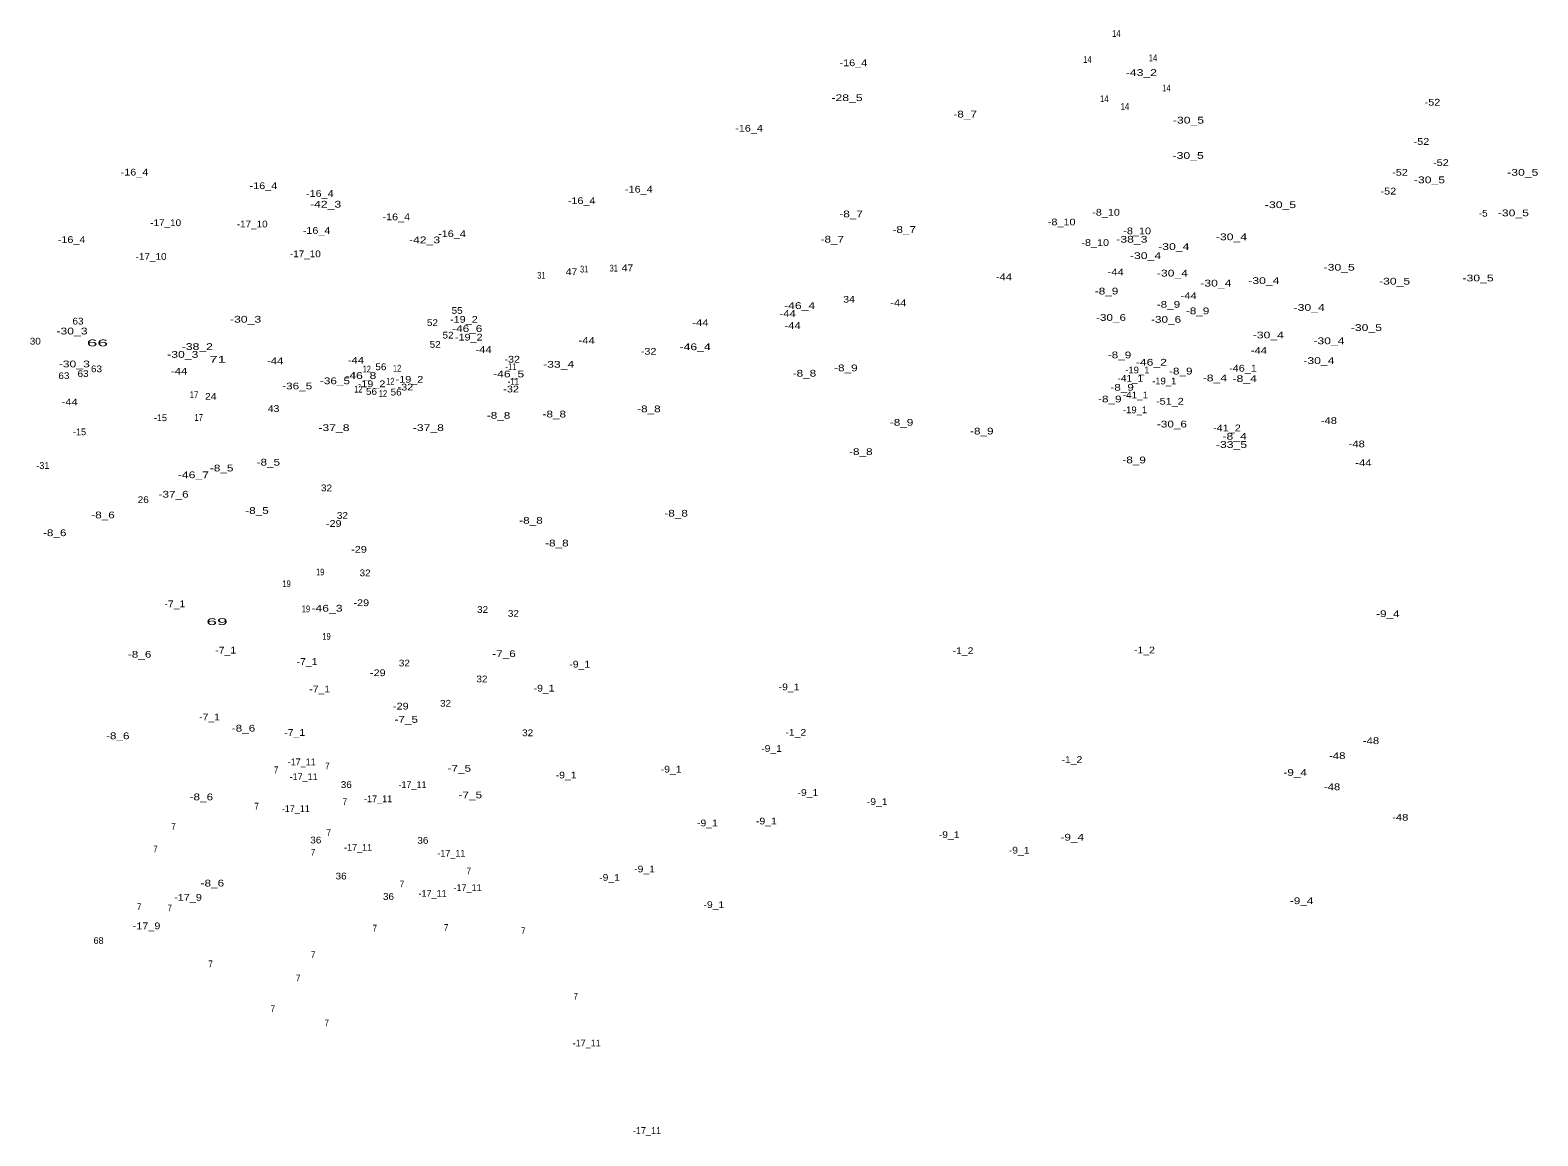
# Model space of a CAD drawing. Extents: x -663241 to -661169, y -1003538 to -1000899.
# Drawn here: x -662062 to -661169, y -1002212 to -1001556 of the extents above; entities that cross this region are included whole.
import ezdxf
from ezdxf.enums import TextEntityAlignment as Align

# ---------------------------------------------------------------- set-up
doc = ezdxf.new("R2010")
doc.units = 0
doc.header["$LTSCALE"] = 1.6
doc.layers.add('24', color=7, linetype='Continuous')

msp = doc.modelspace()

# ---------------------------------------------------------------- texts
at = {"layer": '24'}
for s, width, p in [('14', 0.85, (-661418.459, -1001560.33)), ('-16_4', 1.2, (-661574.25, -1001577.69)), ('14', 0.85, (-661435.569, -1001575.72)), ('14', 0.85, (-661396.74, -1001574.76)), ('-43_2', 1.35, (-661403.58, -1001583.46)), ('14', 0.85, (-661388.76, -1001592.64)), ('-28_5', 1.35, (-661578, -1001598.37)), ('14', 0.85, (-661425.569, -1001598.99)), ('14', 0.85, (-661413.37, -1001603.6)), ('-52', 1.2, (-661231.11, -1001601.06)), ('-8_7', 1.3, (-661508.01, -1001608.11)), ('-30_5', 1.35, (-661375.679, -1001611.68)), ('-16_4', 1.2, (-661636.07, -1001616.49)), ('-52', 1.2, (-661237.65, -1001624.33)), ('-30_5', 1.35, (-661375.87, -1001632.62)), ('-52', 1.2, (-661226.11, -1001636.83)), ('-16_4', 1.2, (-662000.23, -1001642.49)), ('-52', 1.2, (-661250.33, -1001642.6)), ('-30_5', 1.35, (-661232.9, -1001647.05)), ('-30_5', 1.35, (-661177.6, -1001642.63)), ('-16_4', 1.2, (-661923.81, -1001650.55)), ('-16_4', 1.2, (-661890.4, -1001655.16)), ('-16_4', 1.2, (-661701.36, -1001652.6)), ('-52', 1.2, (-661257.25, -1001653.75)), ('-42_3', 1.35, (-661886.98, -1001661.5)), ('-16_4', 1.2, (-661735.26, -1001659.39)), ('-8_7', 1.3, (-661575.59, -1001667.27)), ('-8_10', 1.2, (-661424.52, -1001666.27)), ('-30_5', 1.35, (-661321.15, -1001661.81)), ('-5', 1.1, (-661201.04, -1001666.84)), ('-30_5', 1.35, (-661183.169, -1001666.64)), ('-17_10', 1.1, (-661981.74, -1001672.48)), ('-17_10', 1.1, (-661930.471, -1001673.25)), ('-16_4', 1.2, (-661845.09, -1001668.99)), ('-8_7', 1.3, (-661544.11, -1001676.49)), ('-8_10', 1.2, (-661450.819, -1001672.03)), ('-16_4', 1.2, (-662037.48, -1001682.44)), ('-16_4', 1.2, (-661892.33, -1001677.06)), ('-42_3', 1.35, (-661828.34, -1001682.65)), ('-16_4', 1.2, (-661812.07, -1001678.98)), ('-8_7', 1.3, (-661586.73, -1001682.25)), ('-8_10', 1.2, (-661430.949, -1001684.23)), ('-38_3', 1.35, (-661409.24, -1001682.27)), ('-8_10', 1.2, (-661406.079, -1001677.32)), ('-30_4', 1.35, (-661350.22, -1001680.84)), ('-17_10', 1.1, (-661990.38, -1001692.46)), ('-17_10', 1.1, (-661898.981, -1001690.92)), ('-30_4', 1.35, (-661401.14, -1001691.98)), ('-30_4', 1.35, (-661384.39, -1001686.6)), ('47', 1.15, (-661741.26, -1001701.51)), ('31', 0.8, (-661733.76, -1001699.96)), ('31', 0.8, (-661716.26, -1001699.38)), ('47', 1.15, (-661708.1, -1001699.2)), ('-44', 1.25, (-661418.829, -1001701.66)), ('-30_4', 1.35, (-661385.2, -1001702.35)), ('-30_5', 1.35, (-661286.39, -1001698.88)), ('31', 0.8, (-661759.14, -1001703.62)), ('-44', 1.25, (-661485.059, -1001704.53)), ('-30_4', 1.35, (-661359.47, -1001708.28)), ('-30_4', 1.35, (-661331.02, -1001706.77)), ('-30_5', 1.35, (-661253.559, -1001707.14)), ('-30_5', 1.35, (-661204.1, -1001705.25)), ('34', 1.15, (-661576.809, -1001717.85)), ('-44', 1.25, (-661547.61, -1001719.93)), ('-8_9', 1.3, (-661424.22, -1001712.99)), ('-8_9', 1.3, (-661387.55, -1001720.87)), ('-44', 1.25, (-661375.579, -1001715.69)), ('-30_3', 1.35, (-661934.4, -1001729.67)), ('-19_2', 1.2, (-661805.03, -1001729.74)), ('55', 1.1, (-661809.059, -1001724.48)), ('-44', 1.25, (-661613.169, -1001726.27)), ('-46_4', 1.35, (-661606.12, -1001721.58)), ('-30_6', 1.3, (-661421.59, -1001728.63)), ('-30_6', 1.3, (-661388.95, -1001729.78)), ('-8_9', 1.3, (-661370.27, -1001724.71)), ('-30_4', 1.35, (-661304.17, -1001722.71)), ('-30_3', 1.35, (-662037.26, -1001736.69)), ('63', 1.1, (-662033.68, -1001730.81)), ('52', 1.1, (-661823.669, -1001731.69)), ('-46_6', 1.3, (-661803.041, -1001735.23)), ('-44', 1.25, (-661664.88, -1001731.66)), ('-44', 1.25, (-661610.28, -1001733.39)), ('-30_4', 1.35, (-661328.37, -1001739.02)), ('-30_5', 1.35, (-661270.27, -1001734.61)), ('30', 1.1, (-662058.99, -1001742.67)), ('66', 2.1, (-662022.171, -1001743.69)), ('-38_2', 1.35, (-661962.98, -1001745.87)), ('52', 1.1, (-661822.04, -1001744.58)), ('52', 1.1, (-661814.439, -1001739.1)), ('-19_2', 1.2, (-661802.15, -1001740.31)), ('-44', 1.25, (-661793.39, -1001747.62)), ('-44', 1.25, (-661732.26, -1001742.23)), ('-46_4', 1.35, (-661668.02, -1001746)), ('-30_4', 1.35, (-661292.46, -1001742.47)), ('-30_3', 1.35, (-662035.91, -1001756.18)), ('-30_3', 1.35, (-661971.62, -1001750.52)), ('71', 1.65, (-661950.903, -1001753.43)), ('-44', 1.25, (-661916.86, -1001754.35)), ('-44', 1.25, (-661869, -1001753.96)), ('-32', 1.2, (-661776.4, -1001753.37)), ('-33_4', 1.35, (-661748.87, -1001756.38)), ('-32', 1.2, (-661695.6, -1001748.67)), ('-8_9', 1.3, (-661416.54, -1001750.83)), ('-46_2', 1.35, (-661397.67, -1001755.17)), ('-44', 1.25, (-661333.939, -1001748.16)), ('-30_4', 1.35, (-661298.41, -1001754.19)), ('63', 1.1, (-662042.04, -1001763.12)), ('63', 1.1, (-662030.7, -1001761.87)), ('63', 1.1, (-662022.72, -1001759.08)), ('-44', 1.25, (-661973.76, -1001760.5)), ('-46_8', 1.35, (-661866.12, -1001763.02)), ('12', 0.8, (-661862.569, -1001759.2)), ('56', 1.1, (-661854.21, -1001757.86)), ('12', 0.8, (-661844.6, -1001758.72)), ('-19_2', 1.2, (-661837.291, -1001765.28)), ('-46_5', 1.35, (-661778.54, -1001762.12)), ('-11', 0.85, (-661777.171, -1001757.79)), ('-8_8', 1.3, (-661603.24, -1001761.69)), ('-8_9', 1.3, (-661578.69, -1001758.51)), ('-41_1', 1.1, (-661410.14, -1001764.66)), ('-19_1', 1.05, (-661405.99, -1001759.76)), ('-8_9', 1.3, (-661380.25, -1001760.43)), ('-8_4', 1.35, (-661360.03, -1001764.48)), ('-46_1', 1.2, (-661343.39, -1001758.69)), ('-8_4', 1.35, (-661342.37, -1001764.86)), ('17', 0.85, (-661964.91, -1001774.35)), ('-36_5', 1.3, (-661903.81, -1001769.25)), ('-36_5', 1.3, (-661881.42, -1001766.17)), ('12', 0.8, (-661867.569, -1001771.12)), ('-19_2', 1.2, (-661859.75, -1001767.96)), ('56', 1.1, (-661859.79, -1001772.47)), ('12', 0.8, (-661852.959, -1001773.71)), ('12', 0.8, (-661848.64, -1001766.41)), ('56', 1.1, (-661845.18, -1001772.86)), ('-32', 1.2, (-661839.71, -1001769.89)), ('-32', 1.2, (-661777.07, -1001771.05)), ('-11', 0.85, (-661775.731, -1001766.54)), ('-8_9', 1.3, (-661415, -1001770.04)), ('-41_1', 1.1, (-661407.069, -1001774.57)), ('-19_1', 1.05, (-661390.051, -1001766.29)), ('-44', 1.25, (-662038.61, -1001778.69)), ('24', 1.15, (-661955, -1001775.38)), ('43', 1.15, (-661917.78, -1001782.61)), ('-8_8', 1.3, (-661695.4, -1001782.81)), ('-8_9', 1.3, (-661422.3, -1001776.95)), ('-19_1', 1.05, (-661407.331, -1001783.38)), ('-51_2', 1.2, (-661386.689, -1001778.28)), ('17', 0.85, (-661962.12, -1001787.9)), ('-8_8', 1.3, (-661784.49, -1001786.66)), ('-8_8', 1.3, (-661751.47, -1001785.89)), ('-8_9', 1.3, (-661545.67, -1001790.78)), ('-30_6', 1.3, (-661385.5, -1001791.82)), ('-48', 1.25, (-661292.52, -1001789.74)), ('-37_8', 1.35, (-661882.03, -1001793.96)), ('-37_8', 1.35, (-661826.09, -1001793.96)), ('-8_9', 1.3, (-661498.14, -1001795.97)), ('-41_2', 1.2, (-661352.88, -1001794.08)), ('-8_4', 1.35, (-661348.33, -1001799.06)), ('-8_8', 1.3, (-661569.829, -1001808.17)), ('-33_5', 1.35, (-661350.189, -1001803.93)), ('-48', 1.25, (-661275.99, -1001803.58)), ('-8_5', 1.3, (-661948.549, -1001817.88)), ('-8_5', 1.3, (-661920.9, -1001814.42)), ('-8_9', 1.3, (-661407.9, -1001813.06)), ('-44', 1.25, (-661272.04, -1001814.7)), ('-46_7', 1.35, (-661965.311, -1001821.88)), ('26', 1.1, (-661995.01, -1001836.6)), ('-37_6', 1.3, (-661977.03, -1001833.39)), ('32', 1.1, (-661886.429, -1001829.63)), ('-8_6', 1.3, (-662018.87, -1001845.67)), ('-8_5', 1.3, (-661927.62, -1001843.04)), ('32', 1.1, (-661877.01, -1001845.97)), ('-8_8', 1.3, (-661679.28, -1001844.66)), ('-29', 1.2, (-661882.15, -1001850.75)), ('-8_8', 1.3, (-661765.29, -1001848.89)), ('-8_6', 1.3, (-662047.48, -1001856.23)), ('-8_8', 1.3, (-661749.929, -1001862.33)), ('-29', 1.2, (-661867.17, -1001866.06)), ('19', 0.8, (-661890.191, -1001879.5)), ('32', 1.1, (-661863.559, -1001880.01)), ('19', 0.8, (-661910.091, -1001886.42)), ('-7_1', 1.15, (-661976.31, -1001898.36)), ('-29', 1.2, (-661865.83, -1001897.72)), ('19', 0.8, (-661898.65, -1001901.33)), ('-46_3', 1.35, (-661886.15, -1001900.96)), ('32', 1.1, (-661793.97, -1001901.72)), ('32', 1.1, (-661775.699, -1001904.02)), ('-9_4', 1.3, (-661257.54, -1001904.2)), ('69', 2.1, (-661951.301, -1001908.9)), ('19', 0.8, (-661886.441, -1001917.67)), ('-7_1', 1.15, (-661946.16, -1001925.82)), ('-1_2', 1.15, (-661509.27, -1001926.11)), ('-1_2', 1.15, (-661401.75, -1001925.72)), ('-8_6', 1.3, (-661997.17, -1001928.26)), ('-7_1', 1.15, (-661897.97, -1001932.55)), ('32', 1.1, (-661840.299, -1001933.45)), ('-7_6', 1.3, (-661781.26, -1001927.92)), ('-9_1', 1.15, (-661736.39, -1001934.13)), ('-29', 1.2, (-661856.04, -1001939.21)), ('32', 1.1, (-661794.35, -1001942.87)), ('-7_1', 1.15, (-661890.48, -1001948.87)), ('-9_1', 1.15, (-661757.51, -1001948.34)), ('-9_1', 1.15, (-661612.351, -1001947.58)), ('-29', 1.2, (-661842.4, -1001959)), ('32', 1.1, (-661815.88, -1001957.29)), ('-7_1', 1.15, (-661955.76, -1001965.39)), ('-7_5', 1.3, (-661839.21, -1001966.85)), ('-8_6', 1.3, (-662010.13, -1001976.59)), ('-8_6', 1.3, (-661935.63, -1001972.06)), ('-7_1', 1.15, (-661905.27, -1001974.61)), ('32', 1.1, (-661767.25, -1001974.79)), ('-1_2', 1.15, (-661608.35, -1001974.51)), ('-48', 1.25, (-661267.53, -1001979.5)), ('-9_1', 1.15, (-661622.721, -1001984.07)), ('-48', 1.25, (-661287.52, -1001988.35)), ('7', 0.9, (-661916.3, -1001996.73)), ('7', 0.9, (-661885.93, -1001994.42)), ('-7_5', 1.3, (-661807.72, -1001995.85)), ('-9_1', 1.15, (-661682.24, -1001996.36)), ('-1_2', 1.15, (-661444.76, -1001990.64)), ('36', 1.1, (-661874.71, -1002005.48)), ('-9_1', 1.15, (-661744.451, -1001999.82)), ('-9_4', 1.3, (-661312.46, -1001998.27)), ('-48', 1.25, (-661290.6, -1002006.81)), ('-8_6', 1.3, (-661960.6, -1002012.78)), ('7', 0.9, (-661875.55, -1002015.57)), ('-7_5', 1.3, (-661801.19, -1002011.6)), ('-9_1', 1.15, (-661601.211, -1002010.19)), ('-9_1', 1.15, (-661560.12, -1002015.57)), ('7', 0.9, (-661927.84, -1002018.26)), ('-48', 1.25, (-661250.23, -1002024.88)), ('7', 0.9, (-661977.05, -1002030.19)), ('-9_1', 1.15, (-661660.74, -1002028.25)), ('-9_1', 1.15, (-661625.791, -1002027.1)), ('36', 1.1, (-661892.78, -1002038.36)), ('7', 0.9, (-661885.16, -1002034.03)), ('36', 1.1, (-661829.34, -1002038.55)), ('-9_1', 1.15, (-661517.5, -1002035.16)), ('-9_4', 1.3, (-661444.56, -1002036.68)), ('7', 0.9, (-661987.82, -1002043.65)), ('7', 0.9, (-661894.39, -1002045.57)), ('-9_1', 1.15, (-661476.02, -1002044.38)), ('36', 1.1, (-661877.79, -1002059.71)), ('7', 0.9, (-661802.11, -1002056.73)), ('-9_1', 1.15, (-661718.721, -1002060.52)), ('-9_1', 1.15, (-661697.981, -1002055.52)), ('-8_6', 1.3, (-661954.07, -1002063.87)), ('7', 0.9, (-661841.72, -1002064.42)), ('7', 0.9, (-661997.43, -1002077.88)), ('-17_9', 1.2, (-661968.5, -1002072.31)), ('36', 1.1, (-661849.72, -1002071.82)), ('-9_1', 1.15, (-661656.9, -1002076.65)), ('-9_4', 1.3, (-661308.62, -1002074.33)), ('7', 0.9, (-661979.36, -1002078.65)), ('-17_9', 1.2, (-661993.08, -1002089.22)), ('7', 0.9, (-661857.86, -1002090.57)), ('7', 0.9, (-661815.57, -1002090.19)), ('7', 0.9, (-661769.82, -1002092.11)), ('7', 0.9, (-661955.14, -1002111.73)), ('7', 0.9, (-661894.39, -1002106.34)), ('7', 0.9, (-661903.23, -1002120.19)), ('7', 0.9, (-661738.79, -1002130.96)), ('7', 0.9, (-661918.23, -1002138.26)), ('7', 0.9, (-661886.31, -1002146.73))]:
    msp.add_text(s, height=4, dxfattribs=dict(at, width=width)).set_placement(p, align=Align.CENTER)
for s, p in [('-15', (-661984.851, -1001788.06)), ('-15', (-662032.78, -1001796.43)), ('-31', (-662054.52, -1001816.37)), ('-17_11', (-661901.15, -1001992.02)), ('-17_11', (-661900, -1002000.85)), ('-17_11', (-661835.49, -1002005.46)), ('-17_11', (-661855.841, -1002013.92)), ('-17_11', (-661904.611, -1002019.68)), ('-17_11', (-661867.74, -1002042.73)), ('-17_11', (-661812.451, -1002046.18)), ('-17_11', (-661802.851, -1002066.54)), ('-17_11', (-661823.581, -1002070)), ('68', (-662021.493, -1002097.94)), ('-17_11', (-661732.26, -1002158.66)), ('-17_11', (-661696.551, -1002210.52))]:
    msp.add_text(s, height=4, dxfattribs=at).set_placement(p, align=Align.CENTER)

doc.saveas('drawing.dxf')
